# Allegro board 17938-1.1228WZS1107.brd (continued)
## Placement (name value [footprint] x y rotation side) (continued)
PC5205  SC22U6D3V3MX-1-DL-GP  [C603H40]  123.32 131.98 270 bottom
PC5206  SC22U6D3V3MX-1-DL-GP  [C603H40]  123.32 130.79 270 bottom
PC5208  SCD1U25V2KX-1-DL-GP  [C402H22]  123.32 129.8 270 bottom
PC5209  SC10U25V5KX-DL-GP  [C805H58]  122.23 138.63 180 bottom
PC5210  SC10U25V5KX-DL-GP  [C805H58]  123.3 142.62 270 bottom
PC5211  SC10U25V3MX-3-GP  [C603H40]  123.7 138.64 180 bottom
PC5212  SC220P50V2KX-3DLGP  [C402H22]  119.81 144.5 180 bottom
PC5213  SCD01U25V2KX-3DLGP  [C402H22]  117.22 143.26 90 top
PC5214  SCD1U25V2KX-1-DL-GP  [C402H22]  124.22 143.87 270 bottom
PC5215  SC1KP50V2KX-1DLGP  [C402H22]  117.1 143.18 270 bottom
PC5216  SC10U25V5KX-DL-GP  [C805H58]  123.31 140.89 270 bottom
PC5217  SC22U6D3V3MX-1-DL-GP  [C603H40]  123.32 135.56 270 bottom
PC5301  SC1U10V2KX-1DLGP  [C402H22]  99.6 35.56 90 top
PC5302  SC10U6D3V3MX-DL-GP  [C603H36]  99.44 38.55 180 bottom
PC5303  SCD1U25V2KX-1-DL-GP  [C402H22]  96.37 33.02 270 top
PC5304  SC68P50V2JN-1DLGP  [C402H22]  91.39 36.86 270 top
PC5305  SC10U6D3V3MX-DL-GP  [C603H36]  92.89 40.29 270 bottom
PC5306  SC10U6D3V3MX-DL-GP  [C603H36]  68.94 40.19 270 bottom
PD4401  BAT54C-12-GP  [SOT-23-9H44]  198.17 41.96 180 bottom
PD4404  L1SS355T1G-GP  [SOD323AKH44]  153.65 102.26 0 top
PD4407  RB520S30-GP  [SOD523AKH26]  192.37 41.29 180 bottom
PD4408  BAT54C-12-GP  [SOT-23-9H44]  194.74 41.4 180 bottom
PD4409  RB520S30-GP  [SOD523AKH26]  192.16 44.78 0 bottom
PD5101  AZ4024-01L-R7G-GP  [SOD323AKH40]  119.69 30.94 0 bottom
PG4401  GAP-CLOSE-PWR-3-GP  [GAP-CLOSE-PWR-3]  184.93 58.96 0 bottom
PG4402  GAP-CLOSE-PWR-3-GP  [GAP-CLOSE-PWR-3]  186.44 58.96 180 bottom
PG4405  GAP-CLOSE-PWR-3-GP  [GAP-CLOSE-PWR-3]  172.8 40.51 90 bottom
PG4406  GAP-CLOSE-PWR-3-GP  [GAP-CLOSE-PWR-3]  171.15 40.54 90 bottom
PG4408  GAP-CLOSE-PWR-3-GP  [GAP-CLOSE-PWR-3]  205.81 45.89 270 bottom
PG4415  GAP-CLOSE-PWR-0805-NP-5-GP  [GAP-CLOSE-PWR-0805-NP-5]  182.68 37.76 270 bottom
PG4419  GAP-CLOSE-PWR-0805-NP-5-GP  [GAP-CLOSE-PWR-0805-NP-5]  186.27 56.26 90 bottom
PG4422  GAP-CLOSE-PWR-0805-NP-5-GP  [GAP-CLOSE-PWR-0805-NP-5]  172.07 34.09 180 bottom
PG4423  GAP-CLOSE-PWR-0805-NP-5-GP  [GAP-CLOSE-PWR-0805-NP-5]  175.47 39.6 180 bottom
PG4527  GAP-CLOSE-PWR-3-GP  [GAP-CLOSE-PWR-3]  55.73 40.68 180 bottom
PG4528  GAP-CLOSE-PWR-3-GP  [GAP-CLOSE-PWR-3]  38.74 40.95 180 bottom
PG4530  GAP-CLOSE-PWR-3-GP  [GAP-CLOSE-PWR-3]  69.17 121.38 180 bottom
PG4532  GAP-CLOSE-PWR-3-GP  [GAP-CLOSE-PWR-3]  73.08 134.02 0 bottom
PG4707  GAP-CLOSE-PWR-3-GP  [GAP-CLOSE-PWR-3]  79.12 132.11 90 bottom
PG4708  GAP-CLOSE-PWR-3-GP  [GAP-CLOSE-PWR-3]  79.15 129.87 270 bottom
PG4808  GAP-CLOSE-PWR-3-GP  [GAP-CLOSE-PWR-3]  96.29 132.39 90 bottom
PG4809  GAP-CLOSE-PWR-3-GP  [GAP-CLOSE-PWR-3]  96.29 129.87 270 bottom
PG4813  GAP-CLOSE-PWR-3-GP  [GAP-CLOSE-PWR-3]  89 132.31 90 bottom
PG4815  GAP-CLOSE-PWR-3-GP  [GAP-CLOSE-PWR-3]  89 129.95 270 bottom
PG5001  GAP-CLOSE-PWR-3-GP  [GAP-CLOSE-PWR-3]  108.36 130.38 270 bottom
PG5011  GAP-CLOSE-PWR-3-GP  [GAP-CLOSE-PWR-3]  108.36 132.46 90 bottom
PG5103  GAP-CLOSE-PWR-3-GP  [GAP-CLOSE-PWR-3]  115.52 42.36 90 top
PG5105  GAP-CLOSE-PWR-3-GP  [GAP-CLOSE-PWR-3]  114.75 42.36 90 top
PG5106  GAP-CLOSE-PWR-3-GP  [GAP-CLOSE-PWR-3]  116.28 42.36 90 top
PG5107  GAP-CLOSE-PWR-3-GP  [GAP-CLOSE-PWR-3]  118.56 42.36 90 top
PG5108  GAP-CLOSE-PWR-3-GP  [GAP-CLOSE-PWR-3]  117.8 42.36 90 top
PG5109  GAP-CLOSE-PWR-3-GP  [GAP-CLOSE-PWR-3]  117.04 42.36 90 top
PG5110  GAP-CLOSE-PWR-3-GP  [GAP-CLOSE-PWR-3]  113.41 42.34 270 top
PG5111  GAP-CLOSE-PWR-3-GP  [GAP-CLOSE-PWR-3]  119.9 42.35 180 top
PG5112  GAP-CLOSE-PWR-3-GP  [GAP-CLOSE-PWR-3]  94.87 39.3 270 top
PG5113  GAP-CLOSE-PWR-3-GP  [GAP-CLOSE-PWR-3]  95.63 39.3 270 top
PG5114  GAP-CLOSE-PWR-3-GP  [GAP-CLOSE-PWR-3]  82.48 35.36 270 top
PG5116  GAP-CLOSE-PWR-3-GP  [GAP-CLOSE-PWR-3]  112.65 42.34 270 top
PG5122  GAP-CLOSE-PWR-3-GP  [GAP-CLOSE-PWR-3]  164.01 107.88 270 bottom
PG5201  GAP-CLOSE-PWR-3-GP  [GAP-CLOSE-PWR-3]  119.08 130 270 top
PG5202  GAP-CLOSE-PWR-3-GP  [GAP-CLOSE-PWR-3]  118.31 130 270 top
PG5203  GAP-CLOSE-PWR-3-GP  [GAP-CLOSE-PWR-3]  117.55 130 270 top
PG5204  GAP-CLOSE-PWR-3-GP  [GAP-CLOSE-PWR-3]  113.74 130 270 top
PG5205  GAP-CLOSE-PWR-3-GP  [GAP-CLOSE-PWR-3]  114.5 130 270 top
PG5206  GAP-CLOSE-PWR-3-GP  [GAP-CLOSE-PWR-3]  120.6 130 270 top
PG5207  GAP-CLOSE-PWR-3-GP  [GAP-CLOSE-PWR-3]  116.79 130 270 top
PG5208  GAP-CLOSE-PWR-3-GP  [GAP-CLOSE-PWR-3]  115.26 130 270 top
PG5209  GAP-CLOSE-PWR-3-GP  [GAP-CLOSE-PWR-3]  116.03 130 270 top
PG5210  GAP-CLOSE-PWR-3-GP  [GAP-CLOSE-PWR-3]  122.25 144.29 270 bottom
PG5211  GAP-CLOSE-PWR-3-GP  [GAP-CLOSE-PWR-3]  119.84 130 270 top
PG5212  GAP-CLOSE-PWR-3-GP  [GAP-CLOSE-PWR-3]  121.49 144.29 270 bottom
PG5214  GAP-CLOSE-PWR-3-GP  [GAP-CLOSE-PWR-3]  123.02 144.29 270 bottom
PG5223  GAP-CLOSE-PWR-6-GP  [GAP-CLOSE-PWR]  113.92 130.1 0 bottom
PG5224  GAP-CLOSE-PWR-3-GP  [GAP-CLOSE-PWR-3]  115.95 129.47 270 bottom
PG5225  GAP-CLOSE-PWR-3-GP  [GAP-CLOSE-PWR-3]  121.36 130 270 top
PG5226  GAP-CLOSE-PWR-3-GP  [GAP-CLOSE-PWR-3]  115.19 129.47 270 bottom
PG5227  GAP-CLOSE-PWR-3-GP  [GAP-CLOSE-PWR-3]  122.13 130 270 top
PG5301  GAP-CLOSE-PWR-3-GP  [GAP-CLOSE-PWR-3]  67.58 41.01 180 top
PG5302  GAP-CLOSE-PWR-3-GP  [GAP-CLOSE-PWR-3]  95.27 33.35 270 bottom
PG5303  GAP-CLOSE-PWR-3-GP  [GAP-CLOSE-PWR-3]  91.36 37.74 0 top
PL4401  COIL-2D2UH-11-GP  [L11510030H158]  185.01 49.33 90 bottom
PL4402  COIL-4D7UH-33-GP  [L7066-1830-UH119]  185.01 49.33 90 bottom
PL4501  IND-1D5UH-23-GP-U  [L7066-1830-UH119]  66.98 129.9 180 bottom
PL4502  IND-1D5UH-23-GP-U  [L7066-1830-UH119]  47.35 37.69 270 bottom
PL4701  IND-D15UH-33-GP  [L7366-1830H119]  79.12 131.01 180 bottom
PL4702  HCB2012KF-800T50-GP-U  [L20125H42]  81.79 145.29 180 bottom
PL4703  HCB2012KF-800T50-GP-U  [L20125H42]  83.8 145.29 180 bottom
PL4801  IND-D15UH-33-GP  [L7366-1830H119]  96.29 131.14 180 bottom
PL4802  IND-D15UH-33-GP  [L7366-1830H119]  89 131.14 180 bottom
PL4803  HCB2012KF-800T50-GP-U  [L20125H42]  101.27 144.63 180 bottom
PL4804  HCB2012KF-800T50-GP-U  [L20125H42]  103.31 144.44 180 bottom
PL5001  IND-D47UH-22-GP-U  [L7066-1830-UH119]  108.36 131.42 180 bottom
PL5101  COIL-1UH-34-GP-U1  [L7066-1830-UH119]  116.08 36.72 0 bottom
PL5201  COIL-1UH-34-GP-U1  [L7066-1830-UH119]  118.54 132.87 180 bottom
PMBD1  HRS-CONN20A-2-GP  [DF30FC-20DP-D4V-81]  159.97 144.42 180 bottom
PQ4405  2N7002KDW-1-GP  [SOT-363H44]  147.45 145.47 270 top
PQ4408  MMBT3906-5-GP-U  [SOT23CBE2D4H46-U]  150.93 104.34 180 top
PQ4415  2N7002KDW-1-GP  [SOT-363H44]  205.16 43.79 270 bottom
PQ4416  2N7002KDW-1-GP  [SOT-363H44]  207.78 46.2 0 bottom
PQ4417  2N7002K-2-GP  [SOT23DGS2D4H44]  11.43 128.78 180 top
PQ4418  2N7002KDW-1-GP  [SOT-363H44]  11.66 125.39 180 top
PR4401  D02R6F-GP  [R1206H24]  185.69 58.99 270 bottom
PR4402  2D2R3-1-U-GP  [R603H22]  200.64 55.66 180 bottom
PR4403  2D2R5J-1-GP  [R805H24]  207.76 51.78 0 top
PR4404  402KR2F-GP  [R402H16]  205.95 52.69 270 top
PR4405  4D7R2F-GP  [R402H16]  198.84 52.77 90 bottom
PR4406  100KR2F-L1-GP  [R402H16]  203.13 51.11 0 top
PR4407  D01R3721F-GP-U  [R3720H40]  171.96 38.4 90 bottom
PR4409  100KR2F-L1-GP  [R402H16]  205.8 46.04 0 top
PR4410  105KR2F-1-GP  [R402H16]  202.94 47.49 90 top
PR4411  499R2F-2-GP  [R402H16]  196.29 44.88 270 top
PR4412  -  [0R0402-PAD]  202.55 44.73 0 bottom
PR4413  7K32R2F-GP  [R402H16]  201.35 48.17 90 top
PR4414  -  [0R0805-PAD]  194.05 53.61 270 top
PR4416  2D2R3J-2-GP  [R603H22]  190.68 50.78 0 top
PR4417  100KR2F-L1-GP  [R402H16]  205.29 48.8 90 top
PR4420  0R3J-0-U-GP  [R603H22]  197.43 49.76 270 top
PR4422  1R2F-GP  [R402H16]  194.66 59.13 90 top
PR4423  1R2F-GP  [R402H16]  194.66 59.92 90 top
PR4424  1R2F-GP  [R402H16]  188.17 42.89 135 top
PR4425  1R2F-GP  [R402H16]  187.61 43.45 135 top
PR4426  196KR2F-GP  [R402H16]  207.86 47.65 90 top
PR4427  100KR2F-L2-GP  [R402H16]  205.87 43.59 90 top
PR4429  100KR2F-L2-GP  [R402H16]  208.42 48.94 0 top
PR4430  -  [0R0402-PAD]  13.55 129.52 180 top
PR4431  100KR2J-1-GP  [R402H16]  13.98 127.87 0 top
PR4432  10KR2F-2-GP  [R402H16]  12.63 123.01 90 top
PR4433  -  [0R0402-PAD]  13.31 124.96 0 top
PR4434  0R2F-1-GP  [R402H16]  204.22 54.82 180 top
PR4435  100KR2F-L3-GP  [R402H16]  208.33 48.6 180 bottom
PR4436  1MR2J-1-GP  [R402H16]  153.14 108.21 180 top
PR4437  0R2F-1-GP  [R402H16]  204.22 53.4 270 top
PR4438  0R2J-2-GP  [R402H16]  200.28 49.35 0 top
PR4439  1KR2F-3-GP  [R402H16]  198.33 53.65 90 top
PR4441  0R3J-0-U-GP  [R603H22]  198.02 50.39 270 bottom
PR4442  0R0402-PAD-1-GP  [0R0402-PAD]  201.05 49.4 180 top
PR4443  0R3J-0-U-GP  [R603H22]  199.63 44.44 0 bottom
PR4444  0R0603-PAD-2-GP-U  [0R0603-PAD-1-U]  197.95 49.17 90 bottom
PR4445  0R2F-1-GP  [R402H16]  199.06 51.56 0 top
PR4446  0R3J-0-U-GP  [R603H22]  197.46 51.03 90 top
PR4447  127KR2F-GP  [R402H16]  195.56 46.61 180 top
PR4448  200KR2F-L-GP  [R402H16]  197.72 46.74 0 top
PR4449  200KR2F-L-GP  [R402H16]  207.25 49.68 270 top
PR4450  10KR2F-2-GP  [R402H16]  150.12 145.59 0 top
PR4451  95K3R2F-GP  [R402H16]  205.29 48.01 270 top
PR4452  0R2F-1-GP  [R402H16]  156.78 32.39 180 top
PR4453  0R2F-1-GP  [R402H16]  197.67 47.91 90 top
PR4462  -  [0R0402-PAD]  207.82 39.32 0 top
PR4463  0R2J-2-GP  [R402H16]  207.56 46.75 270 top
PR4464  0R2F-1-GP  [R402H16]  194.31 45.36 180 bottom
PR4465  0R2F-1-GP  [R402H16]  193.63 44.16 270 bottom
PR4472  100KR2F-L3-GP  [R402H16]  207.8 43.41 180 top
PR4473  100KR2J-1-GP  [R402H16]  156.75 109.27 270 top
PR4474  100KR2F-L1-GP  [R402H16]  147.07 143.82 270 top
PR4475  680KR2F-GP  [R402H16]  207.61 45.86 270 top
PR4476  -  [0R0402-PAD]  143.75 146.48 270 top
PR4477  0R2F-1-GP  [R402H16]  153.32 100.15 90 top
PR4478  1KR2F-3-GP  [R402H16]  200.6 44.83 180 bottom
PR4480  0R2F-1-GP  [R402H16]  198.9 47.94 180 top
PR4484  0R2F-1-GP  [R402H16]  205.1 51.17 90 top
PR4485  182KR2F-GP  [R402H16]  204.86 49.99 0 top
PR4486  -  [0R0402-PAD]  192.57 44.04 270 top
PR4487  -  [0R0402-PAD]  192.57 44.83 270 top
PR4488  -  [0R0402-PAD]  203.04 58.73 90 top
PR4489  -  [0R0402-PAD]  203.04 59.52 90 top
PR4490  0R2F-1-GP  [R402H16]  202.53 53.96 270 top
PR4491  7K15R2F-L-GP  [R402H16]  202.34 51.24 180 top
PR4492  NTC-220K-5-GP-U  [NTC-402H24-U]  201.86 49.58 0 top
PR4493  0R2F-1-GP  [R402H16]  206.23 44.38 90 top
PR4494  470KR2J-L1-GP  [R402H15]  176.53 36.68 270 top
PR4495  0R2J-2-GP  [R402H16]  191 42.62 90 bottom
PR4497  100KR2F-L1-GP  [R402H16]  9.79 123.51 0 top
PR4498  -  [0R0402-PAD]  12.75 127.47 270 top
PR4499  0R2J-L-GP  [R402H15]  13.45 126.68 90 top
PR4501  -  [0R0603-PAD]  63.67 135.54 90 bottom
PR4502  -  [0R0603-PAD]  41.18 34.96 270 top
PR4504  0R0402-PAD-1-GP  [0R0402-PAD]  34.77 41.01 270 bottom
PR4505  100KR2J-1-GP  [R402H16]  70.67 139.04 180 bottom
PR4506  1KR2F-3-GP  [R402H16]  72.1 135.02 270 bottom
PR4507  1KR2F-3-GP  [R402H16]  40.41 39.4 180 bottom
PR4508  200KR2F-L1-GP  [R402H16]  71.89 138.43 270 bottom
PR4509  1KR2F-3-GP  [R402H16]  71.45 139.63 180 bottom
PR4511  1KR2F-3-GP  [R402H16]  35.78 39.53 270 bottom
PR4512  200KR2F-L1-GP  [R402H16]  37.62 38.33 90 bottom
PR4513  1MR2J-1-GP  [R402H16]  37.22 39.67 0 bottom
PR4514  1MR2J-1-GP  [R402H16]  69.75 136.22 0 top
PR4516  0R0402-PAD-1-GP  [0R0402-PAD]  30.66 40.54 270 bottom
PR4551  348KR2F-GP  [R402H16]  38.81 39.68 0 bottom
PR4601  0R0402-PAD-1-GP  [0R0402-PAD]  127.49 140.26 270 top
PR4602  0R0402-PAD-1-GP  [0R0402-PAD]  127.49 141.15 270 top
PR4603  1KR2F-3-GP  [R402H16]  138.1 145.13 180 top
PR4604  100R2F-L3-GP  [R402H16]  135.36 143.87 270 top
PR4605  75R2F-2-GP  [R402H16]  135.79 145.09 180 top
PR4606  45D3R2F-L-GP  [R402H16]  137.32 145.09 180 top
PR4607  100R2F-L3-GP  [R402H16]  136.4 145.09 180 bottom
PR4608  100KR2F-L1-GP  [R402H16]  139.45 145.09 180 bottom
PR4609  10KR2F-L1-GP  [R402H15]  137.16 145.09 180 bottom
PR4610  1R2J-GP  [R402H16]  133.35 145.91 180 bottom
PR4611  NTC-10K-29-GP-U  [NTC-402H22-U]  112.3 130.76 180 bottom
PR4612  0R0402-PAD-1-GP  [0R0402-PAD]  135.56 132.23 180 top
PR4613  0R0402-PAD-1-GP  [0R0402-PAD]  127.74 141.96 90 bottom
PR4614  0R2J-L-GP  [R402H15]  138.69 145.09 0 bottom
PR4615  1KR2F-3-GP  [R402H16]  128.88 143.18 0 bottom
PR4616  15K4R2F-GP  [R402H16]  140.12 143.5 0 bottom
PR4617  NTC-470K-17-GP  [NTC-402H22-U]  92.18 142.22 270 bottom
PR4618  11KR2F-L-GP  [R402H16]  128.5 140.77 0 bottom
PR4620  412R2F-GP  [R402H16]  129.37 142.01 270 bottom
PR4621  27K4R2F-GP  [R402H16]  141.4 144.83 90 bottom
PR4622  10R2F-L1-GP  [R402H16]  134.12 145.09 180 bottom
PR4623  0R0402-PAD-1-GP  [0R0402-PAD]  134.88 145.09 180 bottom
PR4624  49D9R2F-L1-GP  [R402H16]  135.64 145.09 180 bottom
PR4625  2K61R2F-1-GP  [R402H16]  126.88 140.72 0 bottom
PR4626  3K3R2F-2-GP  [R402H16]  139.32 142.39 270 top
PR4627  100R2F-L1-GP-U  [R402H14]  128.76 141.61 0 top
PR4628  9K31R2F-GP  [R402H16]  130.78 145.18 0 bottom
PR4629  100KR2F-L1-GP  [R402H16]  131.54 145.18 0 bottom
PR4630  2KR2F-L1-GP  [R402H16]  142.18 141.55 45 top
PR4631  100R2F-L1-GP-U  [R402H14]  143.49 143.23 270 bottom
PR4632  301R2F-GP  [R402H16]  129.15 138.76 90 top
PR4633  2K55R2F-GP  [R402H16]  143.62 142.64 0 top
PR4636  499R2F-2-GP  [R402H16]  142.84 142.64 0 top
PR4637  1K78R2F-GP  [R402H16]  129.14 139.55 270 top
PR4638  2KR2F-L1-GP  [R402H16]  129.26 137.97 90 top
PR4639  100R2F-L1-GP-U  [R402H14]  139.96 141.91 0 bottom
PR4640  2K49R2F-2-L-GP  [R402H16]  127.79 139.52 90 bottom
PR4641  2K61R2F-1-GP  [R402H16]  142.42 139.98 270 bottom
PR4642  523R2F-GP  [R402H16]  138.86 137.95 270 bottom
PR4643  11KR2F-L-GP  [R402H16]  141.79 138.3 180 bottom
PR4644  40K2R2F-GP  [R402H16]  129.42 137.11 90 bottom
PR4645  1KR2F-L1-GP  [R402H15]  140.08 137.72 180 bottom
PR4646  NTC-10K-29-GP-U  [NTC-402H22-U]  100.28 132.18 180 bottom
PR4647  0R0402-PAD-1-GP  [0R0402-PAD]  141.03 138.61 180 top
PR4648  357R2F-GP  [R402H16]  127.94 135.99 180 bottom
PR4649  0R0402-PAD-1-GP  [0R0402-PAD]  128.96 134.39 180 bottom
PR4650  NTC-10K-29-GP-U  [NTC-402H22-U]  83.06 132.87 180 bottom
PR4651  1KR2F-L1-GP  [R402H15]  126.72 135.59 270 bottom
PR4652  11KR2F-L-GP  [R402H16]  130.15 133.96 90 bottom
PR4653  2K61R2F-1-GP  [R402H16]  131.37 136.73 90 bottom
PR4654  NTC-470K-17-GP  [NTC-402H22-U]  74.32 140.9 180 bottom
PR4655  27K4R2F-GP  [R402H16]  136.59 132.19 90 bottom
PR4656  2K87R2F-1-GP  [R402H16]  135.16 133.8 180 bottom
PR4657  2KR2F-L1-GP  [R402H16]  133.35 135.46 270 bottom
PR4658  499R2F-2-GP  [R402H16]  133.89 131.6 180 bottom
PR4659  100R2F-L1-GP-U  [R402H14]  131.75 135.46 90 bottom
PR4660  1K91R2F-1-GP  [R402H16]  132.72 132.03 90 bottom
PR4661  84K5R2F-GP  [R402H16]  136.46 135.2 270 bottom
PR4662  11K8R2F-GP  [R402H16]  136.42 132.97 270 bottom
PR4663  100R2F-L1-GP-U  [R402H14]  133.05 130 90 bottom
PR4665  0R0402-PAD-1-GP  [0R0402-PAD]  143.49 142.47 90 bottom
PR4666  0R0402-PAD-1-GP  [0R0402-PAD]  141.96 141.71 90 bottom
PR4667  0R0402-PAD-1-GP  [0R0402-PAD]  130.53 130.68 270 bottom
PR4668  0R0402-PAD-1-GP  [0R0402-PAD]  130.53 131.47 270 bottom
PR4669  0R2J-L-GP  [R402H15]  138.99 135.74 270 bottom
PR4670  1KR2F-3-GP  [R402H16]  140.25 138.64 180 top
PR4671  0R0402-PAD-1-GP  [0R0402-PAD]  199.05 55.43 90 top
PR4701  0R0402-PAD-1-GP  [0R0402-PAD]  129.9 134.19 180 top
PR4704  2D2R2F-GP  [R402H16]  75.06 143.71 90 bottom
PR4705  2D2R3F-L-GP  [R603H24]  75.26 143.05 0 top
PR4706  0R0402-PAD-1-GP  [0R0402-PAD]  75.11 142.93 90 bottom
PR4707  0R0402-PAD-1-GP  [0R0402-PAD]  75.12 142.15 90 bottom
PR4708  3K65R2F-1-GP  [R402H16]  129.16 132.23 270 bottom
PR4709  2D2R6J-3-GP  [R1206H28]  79.19 134.54 180 top
PR4802  0R0402-PAD-1-GP  [0R0402-PAD]  94.31 143.31 0 bottom
PR4805  2D2R6J-3-GP  [R1206H28]  93.86 133.81 180 top
PR4806  0R0402-PAD-1-GP  [0R0402-PAD]  95.1 143.31 0 bottom
PR4808  3K65R2F-1-GP  [R402H16]  142.88 140.79 270 bottom
PR4809  10R2F-L1-GP  [R402H16]  142.6 138.02 180 bottom
PR4810  2D2R3-1-U-GP  [R603H22]  89.59 143.9 180 bottom
PR4811  0R0402-PAD-1-GP  [0R0402-PAD]  86.11 143.94 0 bottom
PR4812  0R0402-PAD-1-GP  [0R0402-PAD]  86.9 143.94 0 bottom
PR4813  2D2R2F-GP  [R402H16]  88.45 143.94 0 bottom
PR4814  2D2R6J-3-GP  [R1206H28]  87.51 133.43 90 top
PR4815  10R2F-L1-GP  [R402H16]  141.07 134.52 0 bottom
PR4816  3K65R2F-1-GP  [R402H16]  141.91 134.52 180 bottom
PR4821  100KR2F-L1-GP  [R402H16]  139.5 134.52 180 bottom
PR4822  100KR2F-L1-GP  [R402H16]  138.74 134.52 0 bottom
PR4823  100KR2F-L1-GP  [R402H16]  137.98 134.52 180 bottom
PR4824  100KR2F-L1-GP  [R402H16]  140.26 134.52 0 bottom
PR4825  2D2R2F-GP  [R402H16]  94.66 144.94 90 bottom
PR4826  2D2R3-1-U-GP  [R603H22]  95.3 143.02 0 top
PR5001  2D2R3F-L-GP  [R603H24]  112.07 143.31 270 top
PR5003  3K65R2F-1-GP  [R402H16]  126.57 138.33 0 bottom
PR5004  0R0402-PAD-1-GP  [0R0402-PAD]  124 140.35 180 top
PR5101  100KR2J-1-GP  [R402H16]  112.4 27.71 90 top
PR5102  6K49R2F-1-GP  [R402H16]  111.89 29.69 180 top
PR5103  6K2R2F-GP  [R402H16]  116.79 28.02 270 top
PR5104  10K2R2F-GP  [R402H16]  116.07 29.96 90 top
PR5105  -  [0R0603-PAD]  120.07 30 180 top
PR5106  510KR2F-GP  [R402H16]  116.6 32.26 270 top
PR5108  10R2J-L-GP  [R402H16]  111.51 28.5 90 top
PR5109  47KR2J-2-GP  [R402H16]  162.46 108 225 bottom
PR5110  2D2R5J-1-GP  [R805H24]  114.05 35.23 270 top
PR5112  100KR2F-L1-GP  [R402H16]  163.61 109.08 90 bottom
PR5114  1MR2J-1-GP  [R402H16]  163.48 106.78 90 bottom
PR5117  0R0402-PAD-1-GP  [0R0402-PAD]  161.8 107.32 225 bottom
PR5119  29K4R2F-GP  [R402H16]  164.24 118.11 90 bottom
PR5120  13K7R2F-GP  [R402H16]  162.59 117.27 90 bottom
PR5121  0R0402-PAD-1-GP  [0R0402-PAD]  164.24 119.64 270 bottom
PR5122  0R0402-PAD-1-GP  [0R0402-PAD]  164.24 118.87 270 bottom
PR5201  88K7R2F-GP  [R402H16]  120.94 142.7 90 bottom
PR5202  3K16R2F-GP  [R402H16]  119.05 144.5 180 bottom
PR5203  100KR2F-L1-GP  [R402H16]  118.82 143.18 90 top
PR5204  10KR2F-2-GP  [R402H16]  118.27 143.69 180 bottom
PR5210  0R0402-PAD-1-GP  [0R0402-PAD]  116.03 144.4 270 bottom
PR5301  100KR2F-L1-GP  [R402H16]  99.65 34.85 0 bottom
PR5304  18KR2F-GP  [R402H16]  90.21 37.3 0 top
PR5305  14K3R2F-GP  [R402H16]  91.13 35.46 0 top
PR5308  0R0402-PAD-1-GP  [0R0402-PAD]  98.21 39.26 270 top
PT4701  SE330U2VDM-4-GP  [CT7343H83]  80.23 124.31 270 bottom
PT4702  ST33U25VDM-5-GP  [CT7343H79]  83.06 139.47 180 bottom
PT4802  SE330U2VDM-4-GP  [CT7343H83]  99.26 124.41 270 bottom
PT4803  SE330U2VDM-4-GP  [CT7343H83]  88.32 124.46 90 bottom
PT4807  ST33U25VDM-5-GP  [CT7343H79]  102.4 137.62 180 bottom
PU4301  AON7403-GP-U  [PPAK-8P-3232H36]  31.37 129.95 270 top
PU4302  AON7403-GP-U  [PPAK-8P-3232H36]  34.7 129.41 0 top
PU4401  ISL9538HRTZ-GP-U  [QFN32J4-G2D85H34]  203.24 49.04 270 bottom
PU4403  AON7380-GP  [PPAK-8P-3232H36]  193.37 54.12 180 bottom
PU4404  AON7380-GP  [PPAK-8P-3232H36]  193.44 50.06 180 bottom
PU4405  AON7380-GP  [PPAK-8P-3232H36]  182.95 40.87 0 bottom
PU4406  AON7380-GP  [PPAK-8P-3232H36]  179.23 40.87 0 bottom
PU4412  AON7403-GP-U  [PPAK-8P-3232H36]  175.82 32.59 0 bottom
PU4413  AON7403-GP-U  [PPAK-8P-3232H36]  179.23 38.18 180 bottom
PU4501  SY8286BRAC-GP  [QFN20Z3-G1D1H36]  68.46 136.07 270 bottom
PU4502  SY8288CRAC-GP  [QFN20Z3-G1D1H36]  41.18 36.07 0 bottom
PU4601  ISL95859CHRTZ-T-1-GP  [QFN40J5-G3D6-DIFF-H34]  134.21 140.03 90 bottom
PU4701  AOZ5038QI-05-GP  [QFN31G5-G4P-9H34]  77.68 138.3 180 bottom
PU4801  AOZ5038QI-05-GP  [QFN31G5-G4P-9H34]  97.06 138.43 180 bottom
PU4802  AOZ5038QI-05-GP  [QFN31G5-G4P-9H34]  88.34 138.38 180 bottom
PU5001  ISL95808HRZ-T-1-GP  [DFN8G2-G1710-U1H40]  111.99 142.34 180 bottom
PU5002  AON7408-GP  [PPAK-8P-3232H36]  106.68 138.15 180 bottom
PU5003  AON7408-GP  [PPAK-8P-3232H36]  110.42 136.91 0 bottom
PU5101  APL5934KAI-TRG-GP-U  [SOIC8-G3530H63]  164.03 113.2 0 bottom
PU5102  G5388K11U-GP  [QFN32J4-G3PH32]  115.9 30.04 0 bottom
PU5201  AOZ2262QI-10-GP-U  [QFN22G4-G2PH42]  118.65 139.78 180 bottom
PU5301  APL5934KAI-TRG-GP-U  [SOIC8-G3530H63]  95.44 36.78 90 bottom
PWR1  PTWO-CON6-21-GP  [196415-06031-3]  212.7 59.8 0 bottom
Q401  2N7002KDW-1-GP  [SOT-363H44]  139.22 113.93 270 bottom
Q501  PJA138KA-GP  [SOT23DGS2D4H44]  105.29 38.28 90 bottom
Q502  2N7002K-2-GP  [SOT23DGS2D4H44]  107.98 39.8 0 bottom
Q1701  PJT138KA-GP  [SOT-363H44]  17.49 63.84 0 top
Q1702  2N7002KDW-1-GP  [SOT-363H44]  145.8 84.42 180 bottom
Q1801  2N7002KDW-1-GP  [SOT-363H44]  138.41 105.31 90 bottom
Q2408  2N7002K-2-GP  [SOT23DGS2D4H44]  50.19 92.64 0 top
Q2414  2N7002K-2-GP  [SOT23DGS2D4H44]  45.98 70.13 180 top
Q2416  2N7002KDW-1-GP  [SOT-363H44]  23.22 76.66 180 bottom
Q2417  2N7002KDW-1-GP  [SOT-363H44]  34.4 112.44 0 top
Q2505  2N7002K-2-GP  [SOT23DGS2D4H44]  142.27 110.67 270 bottom
Q2507  PJA3415-GP  [SOT23DGS2D4H44]  156.09 82.2 270 bottom
Q2510  2N7002K-2-GP  [SOT23DGS2D4H44]  162.38 80.11 270 bottom
Q2601  2N7002KDW-1-GP  [SOT-363H44]  128.52 117.01 180 top
Q2602  2N7002K-2-GP  [SOT23DGS2D4H44]  142.55 113.97 180 bottom
Q2603  MMBT3904-5-GP-U  [SOT23CBE2D4H46-U]  167.11 79.6 180 bottom
Q3201  2N7002K-2-GP  [SOT23DGS2D4H44]  17.89 59.41 0 top
Q4301  PJA138KA-GP  [SOT23DGS2D4H44]  24.38 97.73 270 top
Q4302  MMBT3904-5-GP-U  [SOT23CBE2D4H46-U]  21.01 97.61 0 top
Q4304  LMUN5212T1G-GP  [SOT323CBE2D2H40]  28.43 124.28 0 top
Q4305  LTA024EUB-FS8-GP  [SC70-2D2-312H44]  27.1 126.42 270 top
Q4348  PJA3415-GP  [SOT23DGS2D4H44]  31.4 125.73 180 top
Q4349  2N7002KDW-1-GP  [SOT-363H44]  28.67 120.75 270 top
Q5501  MMBT3906LT1-1GPU  [SOT23CBE2D4H44]  152.1 131.03 270 top
Q5502  MMBT3906LT1-1GPU  [SOT23CBE2D4H44]  141.51 127.84 270 top
Q5504  MMBT3904LT1-2-GP  [SOT-23-9H44]  149.8 128.3 0 top
Q5505  MMBT3904LT1-2-GP  [SOT-23-9H44]  146.34 127.87 0 top
Q5701  2N7002K-2-GP  [SOT23DGS2D4H44]  21.8 94.29 0 top
Q5702  2N7002KDW-1-GP  [SOT-363H44]  21.97 89.59 180 top
Q5703  LMBT3904LT1G-GP  [SOT23CBE2D4H44]  16.37 105.44 90 bottom
Q5801  2N7002KDW-1-GP  [SOT-363H44]  39.91 93.16 0 top
Q6102  2N7002K-2-GP  [SOT23DGS2D4H44]  51.03 108.76 90 top
Q6301  2N7002K-2-GP  [SOT23DGS2D4H44]  147.7 107.88 90 top
Q6302  PJA138KA-GP  [SOT23DGS2D4H44]  151.01 107.88 180 top
Q6401  PJA138KA-GP  [SOT23DGS2D4H44]  21.09 35.21 180 bottom
Q6402  2N7002K-2-GP  [SOT23DGS2D4H44]  42.65 65.43 0 top
Q6403  RN2418-GP  [SOT23CBE2D6H62]  10.73 110.17 270 bottom
Q6404  RN2418-GP  [SOT23CBE2D6H62]  14.04 110.24 270 bottom
Q6405  RN2418-GP  [SOT23CBE2D6H62]  197.06 55.4 180 bottom
Q6406  2N7002KDW-1-GP  [SOT-363H44]  26.19 78 270 bottom
Q6407  DDTA144EUA-7-F-GP  [SOT-323H44]  40.24 80.11 180 top
Q6408  LMBT3904LT1G-GP  [SOT23CBE2D4H44]  23.23 52.89 180 bottom
Q6501  PJA138KA-GP  [SOT23DGS2D4H44]  69.12 37.85 0 bottom
Q6502  PJA3415-GP  [SOT23DGS2D4H44]  94.36 28.88 180 bottom
Q6503  2N7002K-2-GP  [SOT23DGS2D4H44]  97.79 28.88 180 bottom
Q6504  2N7002KDW-1-GP  [SOT-363H44]  98.56 32.56 180 bottom
Q6505  RN2418-GP  [SOT23CBE2D6H62]  101.76 39.73 0 bottom
Q7001  2N7002KDW-1-GP  [SOT-363H44]  143.31 83.08 180 top
Q7201  2N7002K-2-GP  [SOT23DGS2D4H44]  46.39 131.74 180 top
Q7401  PJA3415-GP  [SOT23DGS2D4H44]  31.4 123.24 180 top
Q7404  2N7002KDW-1-GP  [SOT-363H44]  26.27 109.88 180 bottom
Q7405  2N7002KDW-1-GP  [SOT-363H44]  26.39 106.5 0 bottom
Q7406  2N7002KDW-1-GP  [SOT-363H44]  30.42 107.85 180 top
Q7407  PJT138KA-GP  [SOT-363H44]  30.05 112.89 0 top
Q7408  2N7002K-2-GP  [SOT23DGS2D4H44]  33.57 108.11 180 top
Q9201  PJA3415-GP  [SOT23DGS2D4H44]  223.65 68.56 180 top
Q9202  2N7002K-2-GP  [SOT23DGS2D4H44]  223.65 66.06 180 top
Q9301  2N7002KDW-1-GP  [SOT-363H44]  160.17 139.87 0 top
R301  1KR2J-1-GP  [R402H16]  65.08 99.14 0 bottom
R302  499R2F-2-GP  [R402H16]  58.22 102.33 0 bottom
R304  49D9R2F-GP  [R402H16]  111.65 90.57 90 top
R305  49D9R2F-GP  [R402H16]  113.24 90.73 270 top
R308  1KR2J-1-GP  [R402H16]  105.67 114.86 90 bottom
R309  51R2J-2-GP  [R402H16]  67.08 97.5 0 bottom
R310  51R2J-2-GP  [R402H16]  72.52 100.51 180 bottom
R311  51R2J-2-GP  [R402H16]  70.72 99.25 270 bottom
R312  51R2J-2-GP  [R402H16]  70.79 100.6 270 bottom
R313  51R2J-2-GP  [R402H16]  68.28 99.11 180 bottom
R314  51R2J-2-GP  [R402H16]  66.32 97.5 0 bottom
R315  1KR2J-1-GP  [R402H16]  71.38 98.12 270 bottom
R316  51R2J-2-GP  [R402H16]  89.31 104.9 270 top
R317  51R2J-2-GP  [R402H16]  71 98.3 0 top
R318  51R2J-2-GP  [R402H16]  71.33 101.1 180 top
R319  -  [0R0402-PAD]  116.02 79.65 45 bottom
R401  24D9R2F-L-GP  [R402H16]  93.45 92.69 270 top
R402  10KR2J-3-GP  [R402H16]  136.02 105.46 270 bottom
R403  100KR2J-1-GP  [R402H16]  136.95 113.31 90 bottom
R404  0R2J-L-GP  [R402H15]  136.95 114.1 270 bottom
R405  10KR2J-3-GP  [R402H16]  139.43 111.86 0 bottom
R406  10KR2J-3-GP  [R402H16]  140.2 111.16 0 bottom
R501  121R2F-GP  [R402H16]  110.98 89.3 90 top
R502  80D6R2F-L-GP  [R402H16]  107.75 90.3 225 top
R503  100R2F-L1-GP-U  [R402H14]  108.89 87.41 180 top
R504  0R0402-PAD-1-GP  [0R0402-PAD]  131.14 40.58 90 bottom
R505  470R2F-GP  [R402H16]  132.77 40.58 90 bottom
R506  220KR2F-GP  [R402H16]  108.31 37.95 270 top
R507  220KR2F-GP  [R402H16]  109 38.78 270 top
R601  49D9R2F-GP  [R402H16]  90.53 104.65 180 top
R602  150R2F-1-GP  [R402H16]  59.88 102.35 180 bottom
R604  150R2F-1-GP  [R402H16]  59.07 102.35 0 bottom
R701  0R0402-PAD-1-GP  [0R0402-PAD]  60.02 107.78 90 bottom
R702  0R0402-PAD-1-GP  [0R0402-PAD]  60.02 109.3 90 bottom
R703  220R2J-L2-GP  [R402H16]  60.02 108.54 270 bottom
R704  56R2J-4-GP  [R402H16]  135.03 145.09 180 top
R705  54D9R2F-L1-GP  [R402H16]  136.55 145.09 180 top
R706  100R2F-L1-GP-U  [R402H14]  134.27 145.09 180 top
R707  100R2F-L1-GP-U  [R402H14]  97.62 109.25 270 bottom
R708  100R2F-L1-GP-U  [R402H14]  99.06 109.68 0 bottom
R807  100R2F-L1-GP-U  [R402H14]  80.62 105.27 270 top
R808  100R2F-L1-GP-U  [R402H14]  77.88 105.28 90 top
R809  100R2F-L1-GP-U  [R402H14]  104.49 101.34 270 top
R810  100R2F-L1-GP-U  [R402H14]  104.69 102.53 0 top
R811  GAP-CLOSE-PWR-0805-NP-GP-U  [GAP-CLOSE-PWR-0805-NP]  93.2 101.6 270 top
R812  GAP-CLOSE-PWR-0805-NP-GP-U  [GAP-CLOSE-PWR-0805-NP]  88.72 101.7 270 top
R815  GAP-CLOSE-PWR-0805-NP-GP-U  [GAP-CLOSE-PWR-0805-NP]  92.22 98.62 180 top
R816  GAP-CLOSE-PWR-0805-NP-GP-U  [GAP-CLOSE-PWR-0805-NP]  94.26 98.6 180 top
R817  GAP-CLOSE-PWR-0805-NP-GP-U  [GAP-CLOSE-PWR-0805-NP]  89.58 99.14 270 top
R1103  0R0603-PAD-1-GP-U  [0R0603-PAD-U]  135.68 92.64 180 bottom
R1104  0R0402-PAD-1-GP  [0R0402-PAD]  66.42 40.49 180 top
R1204  10KR2F-L1-GP  [R402H15]  97.62 48.72 180 top
R1205  0R0402-PAD-1-GP  [0R0402-PAD]  96.55 47.35 270 top
R1206  2R2F-GP  [R402H16]  71.73 41.1 0 top
R1208  10KR2F-L1-GP  [R402H15]  97.79 45.75 90 top
R1209  24D9R2F-L-GP  [R402H16]  70.41 42.29 270 top
R1210  0R0402-PAD-1-GP  [0R0402-PAD]  96.45 44.63 270 top
R1211  10KR2F-L1-GP  [R402H15]  75.31 40.84 90 top
R1212  0R0402-PAD-1-GP  [0R0402-PAD]  75.31 41.63 90 top
R1215  240R2F-1-GP  [R402H16]  63.33 45.15 180 top
R1216  SC2D2U6D3V2MX-DL-GP  [C402H22]  96.4 48.92 270 top
R1302  10KR2F-L1-GP  [R402H15]  175.02 45.86 90 top
R1303  0R0402-PAD-1-GP  [0R0402-PAD]  172.67 45.82 270 top
R1305  2R2F-GP  [R402H16]  145.78 42.67 270 top
R1306  10KR2F-2-GP  [R402H16]  175.03 45.09 90 top
R1307  0R2J-L-GP  [R402H15]  172.75 45.04 270 top
R1309  24D9R2F-L-GP  [R402H16]  143.94 43.56 270 top
R1310  10KR2F-L1-GP  [R402H15]  151.77 44.98 180 top
R1311  0R0402-PAD-1-GP  [0R0402-PAD]  150.6 43.31 0 top
R1312  240R2F-1-GP  [R402H16]  139.53 45.09 180 top
R1502  1KR2J-1-GP  [R402H16]  144.91 78.82 180 bottom
R1504  4K7R2J-L-GP  [R402H15]  137.01 95.41 270 top
R1506  100KR2F-L2-GP  [R402H16]  151.66 81.16 180 bottom
R1508  100KR2F-L2-GP  [R402H16]  149.36 88.39 90 bottom
R1510  100KR2F-L2-GP  [R402H16]  157.97 99.26 180 bottom
R1512  4K7R2J-2-GP  [R402H16]  110.29 78.94 45 bottom
R1513  4K7R2J-L-GP  [R402H15]  138.81 84.76 90 bottom
R1515  20KR2J-L2-GP  [R402H16]  37.83 103.1 180 top
R1516  4K7R2J-2-GP  [R402H16]  37.82 104.7 180 top
R1517  1KR2J-1-GP  [R402H16]  60.33 104.32 90 bottom
R1518  1KR2J-1-GP  [R402H16]  60.34 103.53 90 bottom
R1520  4K7R2J-L-GP  [R402H15]  139.04 81.71 90 bottom
R1521  4K7R2J-L-GP  [R402H15]  137.46 81.56 90 bottom
R1522  4K7R2J-L-GP  [R402H15]  138.81 86.54 90 bottom
R1524  100KR2F-L2-GP  [R402H16]  139.63 82.5 90 bottom
R1551  4K7R2J-2-GP  [R402H16]  137.01 96.18 270 top
R1554  20K5R2F-GP  [R402H16]  140.26 107.62 270 bottom
R1603  113R2F-GP  [R402H16]  122.25 104.75 45 top
R1604  100R2F-L1-GP-U  [R402H14]  115.44 104.98 180 top
R1606  10KR2J-3-GP  [R402H16]  135.86 104.54 90 bottom
R1609  0R0402-PAD-1-GP  [0R0402-PAD]  125.61 121.11 270 top
R1610  0R0402-PAD-1-GP  [0R0402-PAD]  125.61 122.63 270 top
R1611  0R0402-PAD-1-GP  [0R0402-PAD]  125.61 121.87 270 top
R1616  0R0402-PAD-1-GP  [0R0402-PAD]  125.61 120.35 270 top
R1617  10KR2J-3-GP  [R402H16]  192.74 35.74 90 top
R1618  0R0402-PAD-1-GP  [0R0402-PAD]  131.33 101.27 180 bottom
R1619  0R2J-L-GP  [R402H15]  130.1 101.67 270 bottom
R1701  10KR2J-3-GP  [R402H16]  117.09 92.58 90 top
R1702  1KR2J-1-GP  [R402H16]  20.12 63.09 90 top
R1707  10KR2J-3-GP  [R402H16]  138.79 80.52 180 bottom
R1708  0R2J-2-GP  [R402H16]  114.68 87.35 90 top
R1713  0R0402-PAD-1-GP  [0R0402-PAD]  108.8 78.52 90 bottom
R1714  10KR2J-3-GP  [R402H16]  102.57 112.24 180 bottom
R1715  100KR2J-1-GP  [R402H16]  108.68 79.78 0 bottom
R1716  100KR2F-L1-GP  [R402H16]  105.64 116.13 180 bottom
R1717  10KR2J-3-GP  [R402H16]  128.08 101.74 270 bottom
R1718  0R2J-L-GP  [R402H15]  52.84 108.76 90 top
R1719  47KR2F-GP  [R402H16]  103.86 113.82 0 bottom
R1721  10KR2J-3-GP  [R402H16]  139.09 78.92 180 bottom
R1726  10KR2J-3-GP  [R402H16]  16.74 66.06 180 top
R1730  330KR2J-L1-GP  [R402H16]  114.49 78.54 90 bottom
R1731  100KR2F-L1-GP  [R402H16]  116.81 79.99 45 bottom
R1737  100KR2J-1-GP  [R402H16]  146.21 86.39 270 bottom
R1738  10KR2J-3-GP  [R402H16]  116.87 89.72 180 top
R1739  100KR2F-L1-GP  [R402H16]  152.28 139.29 180 top
R1803  60D4R2F-GP  [R402H16]  128.93 115.16 270 bottom
R1804  0R0402-PAD-1-GP  [0R0402-PAD]  135.82 119.74 90 bottom
R1805  33R2F-3-GP  [R402H16]  114.78 80.79 180 bottom
R1806  0R2J-L-GP  [R402H15]  47.62 93.34 270 top
R1815  10MR2J-L-GP  [R402H16]  136.26 77.76 270 top
R1817  10KR2J-3-GP  [R402H16]  135.38 118.36 180 bottom
R1820  10KR2J-3-GP  [R402H16]  124.18 76.3 90 top
R1821  10KR2J-3-GP  [R402H16]  118.95 89.9 180 top
R1822  10KR2J-3-GP  [R402H16]  121.44 76.66 180 top
R1823  10KR2J-3-GP  [R402H16]  120.63 76.66 180 top
R1825  10KR2J-3-GP  [R402H16]  122.23 76.66 180 top
R1826  10KR2J-3-GP  [R402H16]  50.07 79.81 180 bottom
R1827  10KR2J-3-GP  [R402H16]  40.42 91.09 90 top
R1837  150KR2J-GP  [R402H16]  118.54 79.1 45 bottom
R1839  33R2J-2-GP  [R402H16]  132.13 115.16 270 bottom
R1840  33R2J-2-GP  [R402H16]  130.53 115.16 270 bottom
R1841  1MR2J-1-GP  [R402H16]  131.45 115.95 90 bottom
R1842  10R2F-L-GP  [R402H14]  148.94 84.81 180 bottom
R1843  10R2F-L-GP  [R402H14]  150.9 78.89 180 bottom
R1844  10R2F-L-GP  [R402H14]  151.68 79.57 180 bottom
R1845  10R2F-L-GP  [R402H14]  149.33 91.7 90 bottom
R1846  10R2F-L-GP  [R402H14]  157.56 98.05 270 bottom
R1901  200R2F-L-GP  [R402H16]  120.91 87 90 top
R1908  33R2F-3-GP  [R402H16]  111.66 80.3 45 bottom
R1909  1KR2J-1-GP  [R402H16]  26.29 22.2 270 top
R1910  10KR2J-3-GP  [R402H16]  138.38 93.75 90 bottom
R1911  10KR2J-3-GP  [R402H16]  137.26 92.55 0 bottom
R1912  33R2F-3-GP  [R402H16]  36.12 107.51 90 top
R1913  33R2F-3-GP  [R402H16]  36.12 106.69 90 top
R1920  33R2F-3-GP  [R402H16]  112.63 78.97 45 bottom
R1921  33R2F-3-GP  [R402H16]  27.44 19.91 270 top
R1922  10KR2J-3-GP  [R402H16]  211.15 63.1 180 top
R2007  10KR2J-3-GP  [R402H16]  124.18 77.06 90 top
R2008  10KR2J-3-GP  [R402H16]  123.02 76.66 180 top
R2009  10KR2J-3-GP  [R402H16]  128.15 98.32 90 bottom
R2010  10KR2J-3-GP  [R402H16]  129.75 98.4 90 bottom
R2041  10KR2J-3-GP  [R402H16]  129.97 100.88 90 bottom
R2043  10KR2J-3-GP  [R402H16]  145.72 78.82 0 bottom
R2044  10KR2J-3-GP  [R402H16]  146.13 82.73 270 top
R2045  10KR2J-3-GP  [R402H16]  28.22 27.48 270 top
R2046  10KR2J-3-GP  [R402H16]  125.95 91.96 180 top
R2047  10KR2J-3-GP  [R402H16]  135.91 86.39 180 top
R2048  51KR2J-1-GP  [R402H16]  126.38 100.07 90 bottom
R2049  51KR2J-1-GP  [R402H16]  128.5 100.46 180 bottom
R2051  0R2J-2-GP  [R402H16]  125.7 93.84 90 top
R2053  10KR2J-3-GP  [R402H16]  117.53 76.62 180 top
R2057  33R2F-3-GP  [R402H16]  121.02 91.61 270 top
R2058  33R2F-3-GP  [R402H16]  121.48 92.66 90 top
R2059  10KR2J-3-GP  [R402H16]  199.16 61.9 270 top
R2060  10KR2J-3-GP  [R402H16]  139.03 92.28 0 top
R2061  10KR2J-3-GP  [R402H16]  210.92 61.17 0 top
R2062  10KR2J-3-GP  [R402H16]  138.81 85.65 90 bottom
R2063  10KR2J-3-GP  [R402H16]  124.76 90.13 270 top
R2064  10KR2J-3-GP  [R402H16]  124.75 92.29 270 top
R2065  10KR2J-3-GP  [R402H16]  136.31 99.41 90 top
R2066  10KR2J-3-GP  [R402H16]  158.43 138.14 270 bottom
R2067  0R2J-2-GP  [R402H16]  125.67 94.62 90 top
R2068  10KR2J-3-GP  [R402H16]  224.62 42.5 0 top
R2101  150R2F-1-GP  [R402H16]  136.31 85.2 90 top
R2108  200R2F-L-GP  [R402H16]  124.13 99.34 180 top
R2111  10KR2J-3-GP  [R402H16]  130.28 92.58 270 bottom
R2112  10KR2J-3-GP  [R402H16]  131.88 92.71 270 bottom
R2113  10KR2J-3-GP  [R402H16]  121.05 89.94 180 top
R2114  10KR2J-3-GP  [R402H16]  119.44 91.13 270 top
R2115  10KR2J-3-GP  [R402H16]  128.68 92.58 90 bottom
R2116  10KR2J-3-GP  [R402H16]  127.07 92.59 90 bottom
R2117  10KR2J-3-GP  [R402H16]  125.68 97.54 270 top
R2118  10KR2J-3-GP  [R402H16]  125.68 98.32 270 top
R2125  0R2J-2-GP  [R402H16]  151.75 113.83 270 bottom
R2202  0R0603-PAD-1-GP-U  [0R0603-PAD-U]  122.6 100.35 135 top
R2203  0R3J-0-U-GP  [R603H22]  114.56 98.29 270 top
R2204  -  [0R0603-PAD]  136.71 88.98 90 top
R2205  -  [0R0603-PAD]  112.6 117.58 270 top
R2402  0R0402-PAD-1-GP  [0R0402-PAD]  41.82 74.63 270 top
R2403  0R2J-L-GP  [R402H15]  25.34 53.17 180 bottom
R2409  0R2J-L-GP  [R402H15]  18.61 56.73 270 top
R2414  10KR2F-2-GP  [R402H16]  43.87 70.31 0 top
R2415  10KR2J-3-GP  [R402H16]  21.8 62.22 0 top
R2417  100KR2J-1-GP  [R402H16]  43.11 68.48 0 top
R2421  330R2J-3-GP  [R402H16]  35.44 76.73 0 top
R2424  20KR2F-L-GP  [R402H16]  22.58 64.14 0 bottom
R2427  0R2J-L-GP  [R402H15]  40.54 64.42 0 top
R2428  0R0402-PAD-1-GP  [0R0402-PAD]  137.89 76.57 90 top
R2430  10KR2J-3-GP  [R402H16]  27.2 56.98 90 top
R2432  1KR2J-1-GP  [R402H16]  19.6 72.09 270 top
R2434  100KR2J-1-GP  [R402H16]  18.02 69.43 0 top
R2435  0R0402-PAD-1-GP  [0R0402-PAD]  40.25 62.79 180 top
R2436  100KR2J-1-GP  [R402H16]  211.05 53.72 0 top
R2437  43R2J-GP  [R402H16]  42.34 72.71 180 top
R2438  0R2J-L-GP  [R402H15]  211.99 52.3 270 top
R2441  100KR2F-L1-GP  [R402H16]  36.63 76.4 90 top
R2442  154KR2F-GP  [R402H16]  40.31 77.45 270 top
R2443  10KR2J-3-GP  [R402H16]  34.65 76.76 0 top
R2444  100KR2F-L1-GP  [R402H16]  33.86 76.79 180 top
R2446  0R0603-PAD-2-GP-U  [0R0603-PAD-1-U]  42.13 70.36 90 top
R2447  0R0402-PAD-1-GP  [0R0402-PAD]  212.04 53.67 0 top
R2448  10KR2F-2-GP  [R402H16]  24.11 63.96 0 bottom
R2449  100KR2J-1-GP  [R402H16]  73.49 34.47 270 top
R2450  100KR2J-1-GP  [R402H16]  72.77 29.34 0 top
R2451  100KR2J-1-GP  [R402H16]  17.58 71.99 0 top
R2452  0R2J-L-GP  [R402H15]  22.77 78.5 90 bottom
R2453  0R2J-L-GP  [R402H15]  23.95 74.28 90 bottom
R2454  100KR2J-1-GP  [R402H16]  23.55 75.56 90 top
R2455  0R0402-PAD-1-GP  [0R0402-PAD]  215.22 51.18 270 top
R2458  1KR2J-1-GP  [R402H16]  21.05 57.6 135 top
R2459  0R0402-PAD-1-GP  [0R0402-PAD]  212.35 55.02 90 top
R2460  0R0402-PAD-1-GP  [0R0402-PAD]  212.32 56.01 270 top
R2461  0R2J-L-GP  [R402H15]  24.77 77.8 0 top
R2462  0R0402-PAD-1-GP  [0R0402-PAD]  34.18 56.08 0 top
R2465  100KR2J-1-GP  [R402H16]  26.04 78.41 270 top
R2466  0R0402-PAD-1-GP  [0R0402-PAD]  60.84 126.16 180 bottom
R2467  100KR2J-1-GP  [R402H16]  45.39 67.29 135 top
R2470  0R0402-PAD-1-GP  [0R0402-PAD]  21.39 65.66 90 top
R2472  0R0402-PAD-1-GP  [0R0402-PAD]  23.43 70.54 180 bottom
R2476  0R2J-L-GP  [R402H15]  24.23 71 180 bottom
R2480  100KR2J-1-GP  [R402H16]  41 66.73 270 top
R2483  330R2J-3-GP  [R402H16]  32.29 76.81 0 top
R2489  100KR2J-1-GP  [R402H16]  43.44 71.53 90 top
R2495  1KR2J-1-GP  [R402H16]  20.31 73.29 0 top
R2496  100KR2J-1-GP  [R402H16]  25.6 71.42 270 bottom
R2497  100KR2J-1-GP  [R402H16]  17.21 69.42 0 top
R2501  33R2F-3-GP  [R402H16]  154.11 100.84 315 bottom
R2502  33R2F-3-GP  [R402H16]  151.36 82.83 0 bottom
R2503  33R2F-3-GP  [R402H16]  155.35 96.19 0 bottom
R2504  10MR2J-L-GP  [R402H16]  160.28 80.39 180 bottom
R2505  0R2J-L-GP  [R402H15]  160.65 78.41 90 bottom
R2506  4K7R2J-2-GP  [R402H16]  158.6 81.54 90 bottom
R2507  33R2F-3-GP  [R402H16]  149.33 92.46 90 bottom
R2508  33R2F-3-GP  [R402H16]  154.1 95.35 270 bottom
R2509  33R2F-3-GP  [R402H16]  151.01 94.46 90 bottom
R2510  33R2F-3-GP  [R402H16]  149.33 93.22 90 bottom
R2511  33R2F-3-GP  [R402H16]  157.15 99.26 180 bottom
R2512  33R2F-3-GP  [R402H16]  157.03 110.14 135 bottom
R2513  33R2F-3-GP  [R402H16]  159.57 109.58 45 bottom
R2514  10KR2J-3-GP  [R402H16]  160.15 94.03 180 bottom
R2515  0R0402-PAD-1-GP  [0R0402-PAD]  156.35 88.13 0 bottom
R2516  0R0402-PAD-1-GP  [0R0402-PAD]  141.3 85.93 90 bottom
R2517  47KR2F-GP  [R402H16]  160.65 79.2 270 bottom
R2518  100KR2J-1-GP  [R402H16]  158.75 83.47 270 bottom
R2519  4K7R2J-2-GP  [R402H16]  156.37 86.49 180 bottom
R2520  100KR2J-1-GP  [R402H16]  158.52 94.67 90 bottom
R2521  4K7R2J-2-GP  [R402H16]  148.72 79.22 0 bottom
R2567  1MR2J-1-GP  [R402H16]  158.75 82.63 270 bottom
R2601  0R1J-GP  [R0201H12]  136.05 127.56 90 top
R2602  -  [0R0402-PAD]  141.21 115.31 90 bottom
R2603  7K5R2F-1-GP  [R402H16]  131.63 124.05 90 bottom
R2604  7K5R2F-1-GP  [R402H16]  133.73 126.62 90 top
R2607  10KR2J-3-GP  [R402H16]  40.4 70.17 0 top
R2608  27KR2F-L-GP  [R402H16]  28.53 92.91 270 bottom
R2610  NTC-100K-8-GP  [NTC-603H38]  58.35 91.75 270 bottom
R2612  0R0402-PAD-1-GP  [0R0402-PAD]  162.56 93.82 90 bottom
R2613  -  [0R0402-PAD]  153.52 79.68 0 bottom
R2614  -  [0R0402-PAD]  153.95 81.38 0 bottom
R2615  0R1J-GP  [R0201H12]  141.12 115.98 90 bottom
R2616  0R1J-GP  [R0201H12]  155.44 137.72 180 bottom
R2701  -  [0R0805-PAD]  34.96 19.63 0 top
R2702  100KR2J-1-GP  [R402H16]  22.08 9.93 0 top
R2703  0R0402-PAD-1-GP  [0R0402-PAD]  17.86 9.22 0 top
R2704  0R0402-PAD-1-GP  [0R0402-PAD]  35.07 7.84 90 top
R2705  0R0402-PAD-1-GP  [0R0402-PAD]  35.06 8.71 90 top
R2708  0R0402-PAD-1-GP  [0R0402-PAD]  20.4 14.81 90 top
R2709  0R0402-PAD-1-GP  [0R0402-PAD]  30.79 6.81 270 top
R2710  100KR2F-L1-GP  [R402H16]  21.57 19.05 0 top
R2711  200KR2F-L-GP  [R402H16]  21.17 17.83 90 top
R2712  0R0402-PAD-1-GP  [0R0402-PAD]  31.88 16.97 0 top
R2715  0R0603-PAD-1-GP-U  [0R0603-PAD-U]  27.84 21.6 0 top
R2717  100KR2J-1-GP  [R402H16]  30.66 16.66 90 top
R2724  33R2J-2-GP  [R402H16]  24.37 24.99 0 top
R2725  0R0402-PAD-1-GP  [0R0402-PAD]  34.32 12.24 270 top
R2735  2K2R2J-L1-GP  [R402H16]  22.02 20.25 270 top
R2736  -  [0R0805-PAD]  33.41 19.62 0 top
R2738  0R2J-L-GP  [R402H15]  28.42 17.91 0 top
R2739  1KR2J-1-GP  [R402H16]  21.72 26.01 0 top
R2740  1KR2J-1-GP  [R402H16]  22.56 26.01 0 top
R2906  0R0603-PAD-1-GP-U  [0R0603-PAD-U]  16.82 10.24 0 top
R2907  0R0402-PAD-1-GP  [0R0402-PAD]  20.73 9.5 90 top
R2908  10R2F-L1-GP  [R402H16]  23.85 8.05 270 top
R2909  0R0402-PAD-1-GP  [0R0402-PAD]  18.72 9.88 0 top
R2910  10R2F-L1-GP  [R402H16]  27.52 8.13 270 top
R2911  0R0603-PAD-1-GP-U  [0R0603-PAD-U]  16.79 18.54 180 top
R2912  4K7R2J-2-GP  [R402H16]  28.15 5.56 180 top
R2913  4K7R2J-2-GP  [R402H16]  26.34 8.41 180 top
R2914  0R0402-PAD-1-GP  [0R0402-PAD]  18.29 19.13 90 top
R2921  1KR2J-1-GP  [R402H16]  27.51 9.42 90 top
R2922  1KR2J-1-GP  [R402H16]  24.59 9.25 0 top
R2923  0R0402-PAD-1-GP  [0R0402-PAD]  17 16.77 90 top
R2924  0R0402-PAD-1-GP  [0R0402-PAD]  17.02 1.92 270 top
R2925  0R0402-PAD-1-GP  [0R0402-PAD]  17 3.06 270 top
R2926  0R0402-PAD-1-GP  [0R0402-PAD]  17.05 5.49 270 top
R2927  0R0402-PAD-1-GP  [0R0402-PAD]  17.01 4.29 270 top
R3101  0R0402-PAD-1-GP  [0R0402-PAD]  48.42 86.74 0 bottom
R3102  2K49R2F-GP  [R402H16]  43.44 87.07 90 bottom
R3103  1KR2J-1-GP  [R402H16]  49.91 84.51 180 top
R3104  0R2J-2-GP  [R402H16]  48.73 88.32 90 top
R3109  1KR2J-1-GP  [R402H16]  50.06 81.59 0 bottom
R3113  15KR2J-1-GP  [R402H16]  48.8 82.02 90 bottom
R3202  510R2J-1-GP  [R402H16]  16.55 61.11 180 top
R3203  0R2J-2-GP  [R402H16]  19.16 60.71 270 top
R3501  0R0402-PAD-1-GP  [0R0402-PAD]  19.15 54.78 270 bottom
R3502  0R0402-PAD-1-GP  [0R0402-PAD]  19.18 53.23 270 bottom
R3503  0R0402-PAD-1-GP  [0R0402-PAD]  19.97 44.95 270 bottom
R3504  0R0402-PAD-1-GP  [0R0402-PAD]  21.83 42.56 270 bottom
R3505  0R0402-PAD-1-GP  [0R0402-PAD]  21.83 43.32 270 bottom
R3506  0R0402-PAD-1-GP  [0R0402-PAD]  19.97 44.11 270 bottom
R3507  0R0402-PAD-1-GP  [0R0402-PAD]  19.15 53.99 270 bottom
R3508  0R0402-PAD-1-GP  [0R0402-PAD]  19.18 52.42 270 bottom
R3512  0R0402-PAD-1-GP  [0R0402-PAD]  22.23 43.92 0 top
R3513  0R5J-5-GP  [R805H24]  17.58 36.53 90 top
R3601  0R2J-2-GP  [R402H16]  17.23 53.86 90 top
R3602  100KR2J-1-GP  [R402H16]  18.07 52.28 90 top
R3603  20KR2F-L-GP  [R402H16]  24.29 50.48 270 top
R3604  22K1R2F-L-GP  [R402H16]  24.3 51.26 270 top
R3605  100KR2J-1-GP  [R402H16]  19.19 55.05 0 top
R3606  100KR2J-1-GP  [R402H16]  17.49 53.08 90 top
R3607  0R2J-2-GP  [R402H16]  24.29 49.69 90 top
R3610  0R2J-L-GP  [R402H15]  22.76 56.01 180 top
R3611  0R2J-L-GP  [R402H15]  22.76 54.41 0 top
R3612  0R2J-L-GP  [R402H15]  22.36 55.6 90 top
R3613  0R2J-L-GP  [R402H15]  22.36 54.81 90 top
R3614  0R2J-L-GP  [R402H15]  21.43 48.09 270 bottom
R3615  0R2J-L-GP  [R402H15]  21.43 48.88 270 bottom
R3616  0R2J-L-GP  [R402H15]  21.83 47.68 0 bottom
R3617  0R2J-L-GP  [R402H15]  21.83 49.28 180 bottom
R3618  100KR2J-1-GP  [R402H16]  17.77 70.73 90 top
R4002  0R0402-PAD-1-GP  [0R0402-PAD]  137.93 145.16 180 bottom
R4005  1KR2J-1-GP  [R402H16]  137.47 146.41 270 bottom
R4006  20KR2F-L-GP  [R402H16]  140.34 118.03 180 bottom
R4009  10KR2J-3-GP  [R402H16]  28.94 29.44 0 top
R4010  20KR2J-L3-GP  [R402H16]  88.4 39.39 90 top
R4011  0R0402-PAD-1-GP  [0R0402-PAD]  84.6 39.64 135 top
R4014  0R2J-L-GP  [R402H15]  141.13 118.01 180 bottom
R4017  0R2J-L-GP  [R402H15]  88.4 40.18 90 top
R4024  0R0402-PAD-1-GP  [0R0402-PAD]  136.07 128.47 90 bottom
R4029  0R0402-PAD-1-GP  [0R0402-PAD]  114.46 144.03 0 bottom
R4030  0R0402-PAD-1-GP  [0R0402-PAD]  22.09 60.89 270 top
R4031  100KR2J-1-GP  [R402H16]  66.56 38.2 270 bottom
R4033  0R2J-L-GP  [R402H15]  39.78 37.09 180 top
R4034  0R2J-L-GP  [R402H15]  89.82 40.31 0 top
R4036  0R0402-PAD-1-GP  [0R0402-PAD]  113.03 127.1 90 bottom
R4040  0R2J-L-GP  [R402H15]  90.66 40.31 0 top
R4042  0R0402-PAD-1-GP  [0R0402-PAD]  65.87 99.14 180 bottom
R4047  0R0402-PAD-1-GP  [0R0402-PAD]  46.96 91.16 90 top
R4048  20KR2J-L3-GP  [R402H16]  89.41 37.31 180 top
R4301  -  [0R0402-PAD]  134.88 34.47 90 top
R4302  15KR2F-GP  [R402H16]  20.42 95.63 90 top
R4303  10KR2J-3-GP  [R402H16]  19 99.14 0 top
R4304  2K2R2J-2-GP  [R402H16]  25.52 94.63 270 top
R4305  33R2J-2-GP  [R402H16]  24 95.05 0 top
R4307  240KR3-GP  [R603H22]  27.39 128.88 0 top
R4308  47KR2F-GP  [R402H16]  28.37 128.65 0 top
R4309  100KR2J-1-GP  [R402H16]  25.77 96.41 0 top
R4311  100KR2F-L1-GP  [R402H16]  32.52 132.21 90 top
R4312  1KR2F-3-GP  [R402H16]  25.24 119.88 270 top
R4315  18K7R2F-GP  [R402H16]  33.54 133.42 0 top
R4316  20KR2J-L2-GP  [R402H16]  29.44 132.18 270 top
R4318  100KR2J-1-GP  [R402H16]  36.35 126.42 90 top
R4334  10KR2F-2-GP  [R402H16]  37.93 126.42 270 top
R4368  0R2F-1-GP  [R402H16]  36.93 127.64 180 top
R4369  100KR2F-L1-GP  [R402H16]  30.53 121.52 0 top
R4370  100KR2F-L1-GP  [R402H16]  31.98 127.69 270 top
R4376  470KR2F-GP  [R402H16]  24.56 125.68 0 top
R4377  84K5R2F-GP  [R402H16]  41.81 118.04 0 top
R4378  100KR2J-1-GP  [R402H16]  37.4 117.6 180 top
R4380  100KR2F-L1-GP  [R402H16]  26.32 124.77 90 top
R4381  18K7R2F-GP  [R402H16]  26.7 122.12 270 top
R4401  1R2F-L-GP  [R402H16]  186.82 37.64 270 top
R4402  1R2F-L-GP  [R402H16]  186.82 36.86 270 top
R4469  0R2F-1-GP  [R402H16]  29.95 127.71 90 top
R4470  0R2F-1-GP  [R402H16]  28.86 122.4 90 top
R4471  0R2F-1-GP  [R402H16]  29.1 119.06 270 top
R4481  0R2F-1-GP  [R402H16]  25.72 119.1 270 top
R4482  0R2F-1-GP  [R402H16]  26.84 120.34 180 top
R5010  0R3J-L1-GP  [R603H22]  106.89 144.22 180 bottom
R5011  0R3J-L1-GP  [R603H22]  105.62 144.22 180 bottom
R5115  0R3J-L1-GP  [R603H22]  121.31 34.49 0 top
R5116  0R3J-L1-GP  [R603H22]  120.15 34.49 0 top
R5118  0R3J-L1-GP  [R603H22]  118.98 34.49 0 top
R5501  0R3J-L1-GP  [R603H22]  209.46 40.22 0 top
R5502  0R3J-L1-GP  [R603H22]  202.87 38.35 270 top
R5504  100R2J-2-GP  [R402H14]  216.33 40.34 0 top
R5511  0R2J-L-GP  [R402H15]  210.95 47.4 270 bottom
R5512  0R2J-L-GP  [R402H15]  210.95 46.62 270 bottom
R5517  4K7R2J-2-GP  [R402H16]  136.32 94.54 90 top
R5518  4K7R2J-2-GP  [R402H16]  136.18 103.75 270 bottom
R5523  0R3J-L1-GP  [R603H22]  218.6 38.3 90 top
R5533  0R2J-L-GP  [R402H15]  225.22 64.77 90 top
R5544  100KR2J-1-GP  [R402H16]  137.02 117.33 180 bottom
R5545  0R2J-2-GP  [R402H16]  147.62 131.01 270 top
R5546  4K7R2F-GP  [R402H16]  143 126.78 90 top
R5547  100KR2F-L1-GP  [R402H16]  148.56 133.82 90 top
R5548  4K7R2F-GP  [R402H16]  152.35 127.59 270 top
R5549  1MR2F-GP  [R402H16]  147.05 133.02 90 top
R5550  0R2J-2-GP  [R402H16]  153.21 129.67 180 top
R5551  0R2J-2-GP  [R402H16]  139.53 126.39 0 top
R5552  200KR2F-L-GP  [R402H16]  149.22 132.58 270 top
R5553  10KR2F-2-GP  [R402H16]  149.21 131.01 90 top
R5554  10KR2F-2-GP  [R402H16]  142.95 130.1 270 top
R5555  200KR2F-L-GP  [R402H16]  144.38 133.99 180 top
R5556  0R3J-L1-GP  [R603H22]  215.42 37.95 180 bottom
R5557  10KR2J-3-GP  [R402H16]  135.73 106.25 270 bottom
R5558  0R3J-L1-GP  [R603H22]  215.42 40.33 0 bottom
R5559  0R3J-L1-GP  [R603H22]  218.65 36.45 0 top
R5560  -  [0R0402-PAD]  209.69 42.25 180 top
R5561  0R2J-2-GP  [R402H16]  208.92 42.24 180 top
R5562  -  [0R0402-PAD]  210.39 48.77 0 top
R5563  0R2J-2-GP  [R402H16]  201.24 33.31 180 top
R5564  10KR2F-2-GP  [R402H16]  201.67 34.53 90 top
R5565  0R2J-2-GP  [R402H16]  225.5 42.5 0 top
R5605  0R0402-PAD-1-GP  [0R0402-PAD]  52.6 125.15 180 bottom
R5705  470R2F-GP  [R402H16]  22.61 95.12 0 bottom
R5751  2K2R2J-2-GP  [R402H16]  17.66 88.83 90 top
R5755  2K2R2J-2-GP  [R402H16]  19.56 88.6 90 top
R5759  470R2F-GP  [R402H16]  22.61 93.42 180 bottom
R5764  200KR2F-L-GP  [R402H16]  15.19 108.12 270 bottom
R5765  0R0402-PAD-1-GP  [0R0402-PAD]  19.59 94.29 90 bottom
R5766  0R0402-PAD-1-GP  [0R0402-PAD]  19.59 95.05 90 bottom
R5767  0R0402-PAD-1-GP  [0R0402-PAD]  19.61 95.84 90 bottom
R5768  0R0402-PAD-1-GP  [0R0402-PAD]  19.61 96.6 90 bottom
R5769  0R0402-PAD-1-GP  [0R0402-PAD]  19.61 97.38 90 bottom
R5770  0R0402-PAD-1-GP  [0R0402-PAD]  19.61 98.15 90 bottom
R5771  0R0402-PAD-1-GP  [0R0402-PAD]  19.61 98.96 90 bottom
R5772  0R0402-PAD-1-GP  [0R0402-PAD]  19.61 99.72 90 bottom
R5773  470R2F-GP  [R402H16]  21.8 97.31 0 bottom
R5774  470R2F-GP  [R402H16]  21.8 95.61 180 bottom
R5775  470R2F-GP  [R402H16]  22.58 99.52 0 bottom
R5776  470R2F-GP  [R402H16]  22.58 97.82 180 bottom
R5777  470R2F-GP  [R402H16]  23.4 101.75 0 bottom
R5778  470R2F-GP  [R402H16]  23.4 100.05 180 bottom
R5781  150KR2F-L-GP  [R402H16]  16.38 107.95 0 bottom
R5782  100KR2J-1-GP  [R402H16]  14.36 113.44 0 bottom
R5804  4K99R2F-L-GP  [R402H16]  56.85 113.95 90 top
R5805  4K7R2J-2-GP  [R402H16]  52.77 115.53 180 bottom
R5807  4K7R2J-2-GP  [R402H16]  43.77 116.99 90 top
R5808  4K7R2J-2-GP  [R402H16]  43.97 116.21 90 top
R5809  4K7R2J-2-GP  [R402H16]  44 119.39 90 top
R5810  4K7R2J-2-GP  [R402H16]  43.77 118.57 90 top
R5811  4K7R2J-2-GP  [R402H16]  43.77 117.78 90 top
R5812  4K7R2J-2-GP  [R402H16]  46.28 113.72 180 top
R5813  4K7R2J-2-GP  [R402H16]  44 120.17 90 top
R5814  4K7R2J-2-GP  [R402H16]  44.71 121.06 270 top
R5815  4K7R2J-2-GP  [R402H16]  44.12 114.64 90 top
R5816  4K7R2J-2-GP  [R402H16]  52.9 113.77 0 bottom
R5817  2K2R2J-2-GP  [R402H16]  44.12 113.88 90 top
R5818  1MR2J-1-GP  [R402H16]  52.68 119.53 180 bottom
R5819  1MR2J-1-GP  [R402H16]  53.53 119.91 180 bottom
R5820  1MR2J-1-GP  [R402H16]  54.48 115.4 90 bottom
R5821  0R2F-1-GP  [R402H16]  45.48 113.72 180 top
R5822  100KR2J-1-GP  [R402H16]  57.86 120.17 0 top
R5823  100KR2J-1-GP  [R402H16]  57.86 118.59 180 top
R5824  0R2J-L-GP  [R402H15]  56.7 118.87 270 top
R5825  0R2J-L-GP  [R402H15]  56.7 119.64 270 top
R5826  0R2J-L-GP  [R402H15]  52.35 123.39 90 top
R5827  0R2J-L-GP  [R402H15]  50.75 123.39 270 top
R5828  0R2J-L-GP  [R402H15]  55.07 123.26 180 top
R5829  0R2J-L-GP  [R402H15]  55.07 121.68 0 top
R5830  0R2J-L-GP  [R402H15]  59.44 119.86 180 bottom
R5831  0R2J-L-GP  [R402H15]  58.65 119.86 180 bottom
R5832  0R2J-L-GP  [R402H15]  47.76 111.23 270 top
R5833  0R2J-L-GP  [R402H15]  46.15 111.23 90 top
R5834  2K2R2J-2-GP  [R402H16]  40.04 95.07 90 top
R5838  0R2J-L-GP  [R402H15]  49.41 111.23 90 top
R5839  0R2J-L-GP  [R402H15]  50.98 111.23 270 top
R5840  0R2J-L-GP  [R402H15]  51.17 122.99 0 top
R5841  0R2J-L-GP  [R402H15]  51.95 122.99 0 top
R5842  0R2J-L-GP  [R402H15]  54.66 122.85 270 top
R5843  0R2J-L-GP  [R402H15]  54.66 122.09 270 top
R5844  0R2J-L-GP  [R402H15]  58.28 115.09 180 top
R5845  0R2J-L-GP  [R402H15]  58.28 116.71 0 top
R5854  5D1R2J-1-GP  [R402H16]  47.88 113.72 90 top
R5855  5D1R2J-1-GP  [R402H16]  51.87 113.23 180 top
R5856  5D1R2J-1-GP  [R402H16]  52.63 113.23 180 top
R5857  5D1R2J-1-GP  [R402H16]  53.39 113.23 180 top
R5858  5D1R2J-1-GP  [R402H16]  54.16 113.23 180 top
R5859  5D1R2J-1-GP  [R402H16]  47.88 112.96 90 top
R5860  5D1R2J-1-GP  [R402H16]  49.81 113.26 180 top
R5861  5D1R2J-1-GP  [R402H16]  50.57 113.26 180 top
R6001  0R0805-PAD-1-GP-U  [0R0805-PAD-U]  159.12 39 90 top
R6002  0R0402-PAD-1-GP  [0R0402-PAD]  153.68 35.19 90 top
R6003  0R0805-PAD-1-GP-U  [0R0805-PAD-U]  187 33.86 180 top
R6004  0R0402-PAD-1-GP  [0R0402-PAD]  188.22 37.57 0 top
R6101  75KR2J-GP  [R402H16]  48.54 108.55 270 top
R6102  75KR2J-GP  [R402H16]  53.52 107.8 270 top
R6104  0R0402-PAD-1-GP  [0R0402-PAD]  31.78 97.25 90 top
R6105  0R0402-PAD-1-GP  [0R0402-PAD]  31.78 98.03 90 top
R6108  0R2J-L-GP  [R402H15]  43.27 104.88 180 top
R6109  0R2J-L-GP  [R402H15]  44.92 102.88 0 top
R6110  0R2J-L-GP  [R402H15]  48.54 107.77 270 top
R6114  10KR2J-3-GP  [R402H16]  44.91 104.47 0 top
